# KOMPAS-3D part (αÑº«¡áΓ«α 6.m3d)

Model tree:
1. Эскиз:1
2. Операция выдавливания:1
     Толщина стенки 1 = 2; Толщина стенки 2 = 8; Расстояние 1 = 1
3. Эскиз:3
4. Операция выдавливания:2
     Толщина стенки 1 = 2; Толщина стенки 2 = 6; Расстояние 1 = 5.5
5. Эскиз:4
6. Операция выдавливания:3
     Толщина стенки 1 = 2; Толщина стенки 2 = 6; Расстояние 1 = 1
7. Эскиз:5
8. Эскиз:6
9. Операция выдавливания:4
     Толщина стенки 1 = 2; Толщина стенки 2 = 2.5; Расстояние 1 = 50
10. Эскиз:7
11. Вырезать элемент выдавливания:1
     Толщина стенки 2 = 1.5; Расстояние 1 = 40
12. Эскиз:8
13. Операция выдавливания:5
     Толщина стенки 1 = 2; Толщина стенки 2 = 2.5; Расстояние 1 = 50
14. Эскиз:9
15. Вырезать элемент выдавливания:2
     Толщина стенки 2 = 1.5; Расстояние 1 = 40
16. Эскиз:10
17. Операция выдавливания:6
     Толщина стенки 1 = 2; Толщина стенки 2 = 2.5; Расстояние 1 = 10
18. Эскиз:11
19. Операция выдавливания:7
     Толщина стенки 1 = 2; Толщина стенки 2 = 6; Расстояние 1 = 1
20. Эскиз:12
21. Операция выдавливания:8
     Толщина стенки 1 = 2; Толщина стенки 2 = 6; Расстояние 1 = 5.5
22. Эскиз:13
23. Операция выдавливания:9
     Толщина стенки 1 = 2; Толщина стенки 2 = 8; Расстояние 1 = 1
24. Эскиз:14
25. Вырезать элемент выдавливания:3
     Толщина стенки 2 = 1.5; Расстояние 1 = 23
26. Эскиз:15
27. Вырезать элемент выдавливания:4
     Толщина стенки 2 = 1.5; Расстояние 1 = 1
28. Эскиз:16
29. Вырезать элемент выдавливания:5
     Расстояние 1 = 150
30. Эскиз:20
31. Операция выдавливания:13
     Толщина стенки 1 = 5; Расстояние 1 = 10; Расстояние 2 = 0.4
